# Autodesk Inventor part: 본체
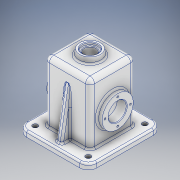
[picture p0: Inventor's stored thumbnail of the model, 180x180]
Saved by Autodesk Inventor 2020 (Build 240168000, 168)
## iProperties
Created: 2022-11
Part Number: 본체
Material: 알루미늄 6061
Document SubType Name: Modeling
Designer: com
Density: 2.7 g/cm^3
Appearance: 알루미늄 - 평지
Mass: 1129.8 g
Surface Area: 1015.53 cm^2
Volume: 418.443 cm^3
Author: com
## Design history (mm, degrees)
sketch "스케치1"
  geometry: L1 (47, 65)-(-47, 65); L2 (-62, 50)-(-62, -50); L3 (-47, -65)-(47, -65); L4 (62, -50)-(62, 50); L5 (62, 65)-(-62, -65); L6 (-62, 65)-(62, -65); A1 r 15 centre (47, -50) between (47, -65) and (62, -50); A2 r 15 centre (-47, -50) between (-62, -50) and (-47, -65); A3 r 15 centre (47, 50) between (62, 50) and (47, 65); A4 r 15 centre (-47, 50) between (-47, 65) and (-62, 50); 1 further point
  constraints: 12 end point, 8 point on circle, 8 point on line, 8 tangent, 4 centre point, 3 equal radius, 2 midpoint, 2 parallel, 1 horizontal, 1 perpendicular
  dimensions: "d0" = 124 distance of L6.end L5.end; "d1" = 130 distance of L5.end L6.start; "d2" = 15 radius of A1
extrude "돌출1" new body sketch "스케치1" distance "d3" = 10; taper "d4" = 0 deg
sketch "스케치2"
  geometry: L1 (-40, -40)-(40, -40); L2 (40, -40)-(40, 40); L3 (40, 40)-(-40, 40); L4 (-40, 40)-(-40, -40); L5 (-40, -40)-(40, 40); L6 (40, -40)-(-40, 40); 1 further point
  constraints: 12 end point, 2 midpoint, 2 parallel, 1 horizontal, 1 perpendicular
  dimensions: "d5" = 80 distance of L3.end L2.end; "d6" = 80 distance of L2.end L1.end
extrude "돌출2" join sketch "스케치2" distance "d7" = 107; taper "d8" = 0 deg
sketch "스케치4"
  geometry: L1 (117, -40)-(117, 40) reference; L2 (117, 0)-(127, 0); L3 (127, 0)-(127, -18.237); L4 (127, -18.237)-(117, -20); L5 (0, 50)-(0, -50) reference; L6 (117, 0)-(117, -20); 1 further point
  constraints: 8 end point, 1 horizontal, 1 midpoint, 1 perpendicular, 1 point on line, 1 vertical
  dimensions: "d10" = 127 distance between parallel lines of L5 L3; "d11" = 20 distance from line of L2 L4.end; "d12" = 100 deg angle of L1 L4
revolve "회전1" sketch "스케치4" stored, may be unused: angle "d13" = 90 deg
sketch "스케치7"
  geometry: L1 (80, 0)-(80, 107) reference; L2 (-10, -10)-(90, -10) reference; C1 r 27.5 at (40, 45); 1 further point
  constraints: 1 centre point
  dimensions: "d18" = 55 diameter of C1; "d19" = 40 distance from line of L1 C1.centre; "d20" = 55 distance from line of L2 C1.centre
extrude "돌출4" join sketch "스케치7" distance "d21" = 9; taper "d22" = 0 deg
sketch "스케치5"
  geometry: L1 (32, -32)-(-32, -32); L2 (-32, -32)-(-32, 32); L3 (-32, 32)-(32, 32); L4 (32, 32)-(32, -32); L5 (32, -32)-(-32, 32); L6 (-32, -32)-(32, 32); 1 further point
  constraints: 12 end point, 2 midpoint, 2 parallel, 1 horizontal, 1 perpendicular
  dimensions: "d14" = 64 distance of L2.end L3.end; "d15" = 64 distance of L1.end L2.end
extrude "돌출3" cut sketch "스케치5" distance "d16" = 109; taper "d17" = 0 deg
sketch "스케치8"
  geometry: C1 r 27.5 at (0, 0) reference; C2 r 16 at (0, 0); 1 further point
  constraints: 1 centre point, 1 coincident
  dimensions: "d24" = 32 diameter of C2
extrude "돌출5" cut sketch "스케치8" extent not by distance; stored distance "d25" = 0; taper "d26" = 0 deg
sketch "스케치9"
  geometry: L1 (10, 50)-(10, 65) reference; L2 (10, 55)-(95.069, 40); L3 (0, 65)-(10, 65) reference; L4 (10, 55)-(10, 40); L5 (10, -50)-(10, 50) reference; L6 (10, 40)-(95.069, 40); L7 (10, 40)-(117, 40) reference; 2 further points
  constraints: 6 end point, 2 point on line, 1 collinear
  dimensions: "d27" = 10 distance from line of L3 L2.start; "d28" = 100 deg angle of L2 L1; "d92" = 85.06923 distance of L4.end L2.end
extrude "돌출6" join sketch "스케치9" stored distance "d29" = 10; taper "d30" = 0 deg
sketch "스케치10"
  geometry: C1 r 18.237 at (0, 0) reference; 2 further points
  constraints: 1 coincident
hole "구멍1" sketch "스케치10" at (0, 0) diameter "d31" = 21; stored, may be unused: countersink angle "d35" = 90 deg, drill point angle "d37" = 118 deg; dims "d32" = 6, "d33" = 28, "d34" = 4, "d36" = 8
sketch "스케치11"
  geometry: C1 r 16 at (0, 0) reference; A1 r 22.5 centre (0, 0) between (0, 22.5) and (-22.5, 0); 3 further points
  constraints: 4 point on circle, 1 centre point, 1 coincident
  dimensions: "d38" = 45 diameter of A1; "d39" = 45 distance of point (0, -22.5) A1.start; "d40" = 45 distance of A1.end point (22.5, 0); "d41" = 22.5 horizontal distance of point (22.5, 0) A1.start; "d42" = 22.5 horizontal distance of A1.end point (0, -22.5)
hole "구멍2" sketch "스케치11" at (0, 22.5), (-22.5, 0), (0, -22.5), (22.5, 0) diameter "d43" = 3.242; stored, may be unused: countersink angle "d47" = 90 deg, drill point angle "d49" = 118 deg; dims "d44" = 8, "d45" = 28, "d46" = 4, "d48" = 10
sketch "스케치13"
  geometry: C1 r 4.5 at (-47, -50); C2 r 4.5 at (47, -50); C3 r 4.5 at (47, 50); C4 r 4.5 at (-47, 50); A1 r 15 centre (-47, -50) between (-62, -50) and (-47, -65) reference; A2 r 15 centre (47, -50) between (47, -65) and (62, -50) reference; A3 r 15 centre (47, 50) between (62, 50) and (47, 65) reference; A4 r 15 centre (-47, 50) between (-47, 65) and (-62, 50) reference; 1 further point
  constraints: 4 centre point, 4 coincident
  dimensions: "d50" = 9 diameter of C1; "d51" = 9 diameter of C2; "d52" = 9 diameter of C3; "d53" = 9 diameter of C4
extrude "돌출7" cut sketch "스케치13" extent not by distance; stored distance "d54" = 0; taper "d55" = 0 deg
sketch "스케치15"
  geometry: L1 (80, 0)-(80, 107) reference; L2 (21.763, 117)-(58.237, 117) reference; L3 (19.389, 95.353)-(60.868, 95.353); L4 (60.868, 95.353)-(60.868, 89.349); L5 (60.868, 89.349)-(19.389, 89.349); L6 (19.389, 89.349)-(19.389, 95.353); L7 (0, 107)-(80, 107) reference; L8 (0, 0)-(0, 107) reference; 2 further points
  constraints: 2 other
  dimensions: "d66" = 40 distance from line of L1 point (40, 92); "d67" = 25 distance from line of L2 point (40, 92); "d70" = 11.64664 distance between parallel lines of L7 L3; "d71" = 19.3891 distance between parallel lines of L8 L6; "d72" = 41.47897 distance of L4.end L5.end; "d73" = 6.00407 distance of L3.end L4.end
feature "엠보싱2" sketch "스케치15" dims "d0" = 124, "d1" = 130, "d2" = 15, "d5" = 80, "d68" = 0.5, "d69" = 0
fillet "모깎기3" dims "d74" = 8
fillet "모깎기4" dims "d75" = 3
fillet "모깎기5" dims "d76" = 3
fillet "모깎기6" dims "d77" = 3
fillet "모깎기7" dims "d78" = 3
fillet "모깎기8" dims "d79" = 3
chamfer "모따기1" distance "d80" = 1; stored, may be unused: second distance "d81" = 2, angle "d82" = 45 deg
chamfer "모따기2" distance "d83" = 1; stored, may be unused: second distance "d84" = 2, angle "d85" = 45 deg
chamfer "모따기3" distance "d86" = 1; stored, may be unused: second distance "d87" = 2, angle "d88" = 45 deg
chamfer "모따기4" distance "d89" = 1; stored, may be unused: second distance "d90" = 2, angle "d91" = 45 deg
fillet "모깎기9" dims "d93" = 3
node "솔리드1"
mirror "미러1"
mirror "미러2"
mirror "미러3"
feature "A9D066F2-1C7D-4E18-AEED-F7BC21143FA4" dims "d31" = 21, "d32" = 6, "d33" = 28, "d34" = 4, "d35" = 90 deg, "d36" = 8, "d37" = 118 deg
